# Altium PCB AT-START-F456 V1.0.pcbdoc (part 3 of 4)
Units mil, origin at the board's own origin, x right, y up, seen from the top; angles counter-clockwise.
Board outline 10942.5 x 3554 mil, 2 copper layers (Top Layer, Bottom Layer); 156 components, 201 nets, 759 pads, 796 vias.
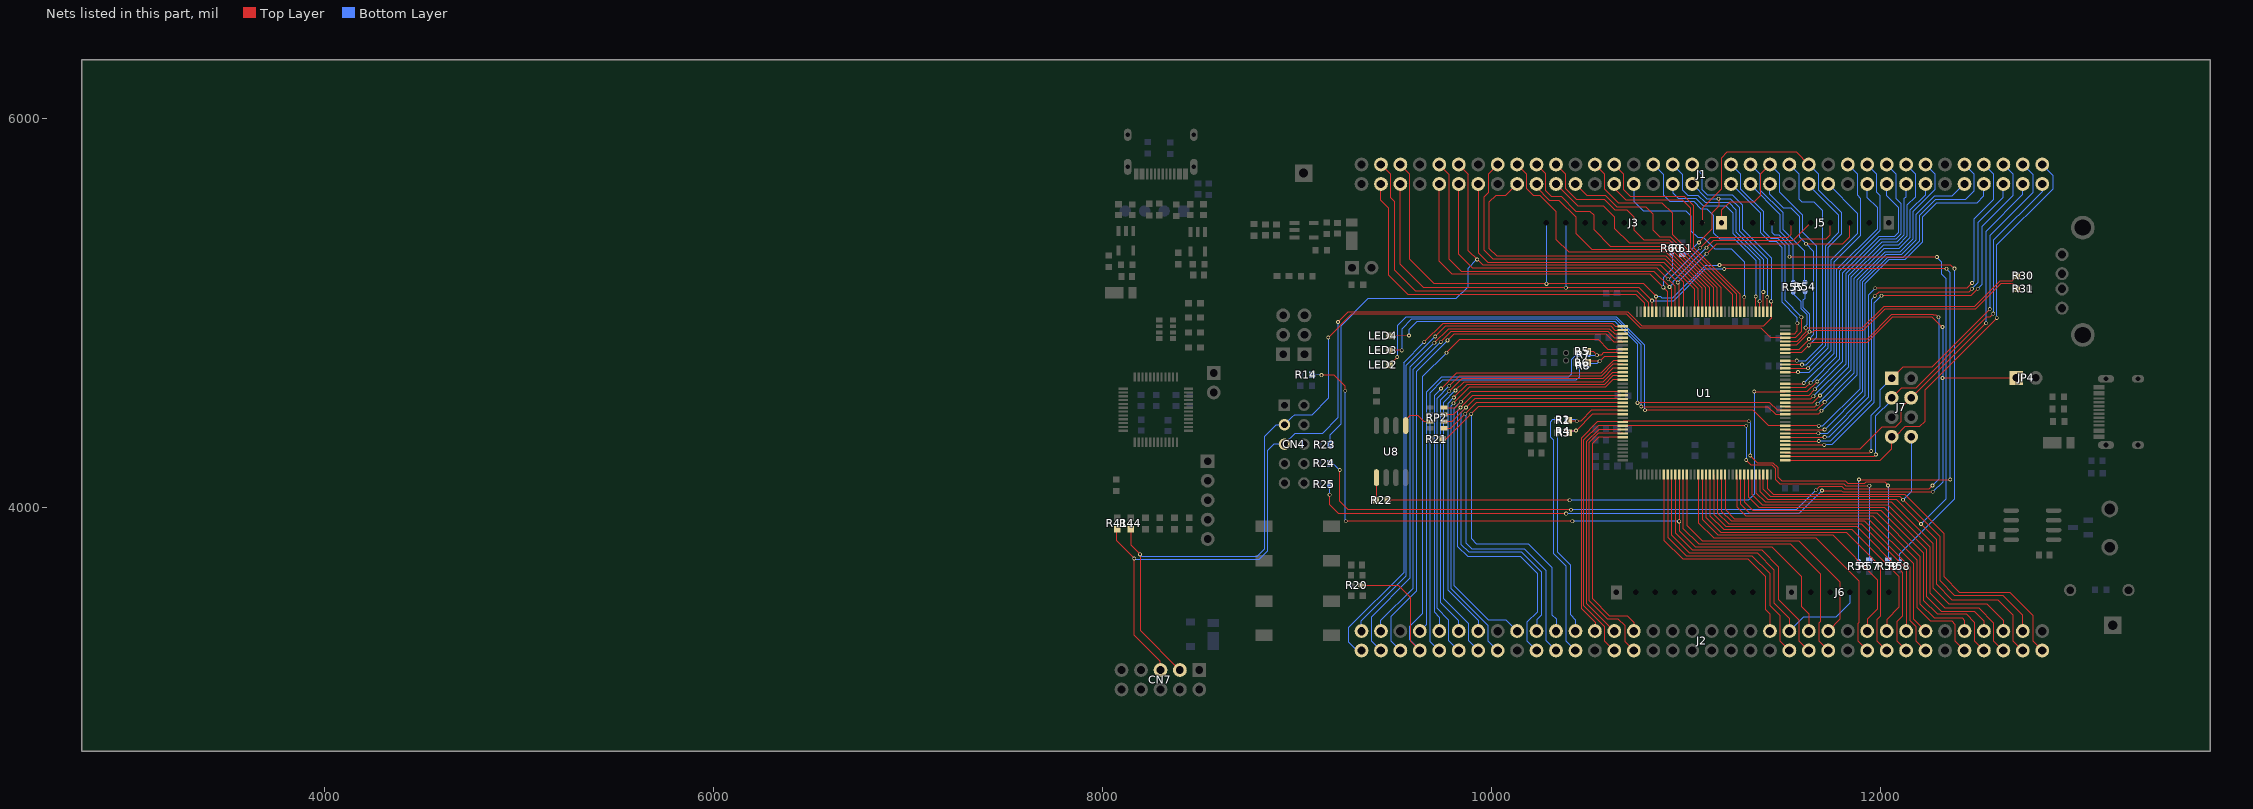
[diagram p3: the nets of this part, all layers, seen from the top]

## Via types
v1: diameter 19.7, hole 11.8, Top Layer to Bottom Layer, 419 vias
v2: diameter 19.68, hole 11.81, Top Layer to Bottom Layer, 364 vias
v3: diameter 31.5, hole 19.68, Top Layer to Bottom Layer, 12 vias
v4: diameter 27.56, hole 19.68, Top Layer to Bottom Layer, 1 vias

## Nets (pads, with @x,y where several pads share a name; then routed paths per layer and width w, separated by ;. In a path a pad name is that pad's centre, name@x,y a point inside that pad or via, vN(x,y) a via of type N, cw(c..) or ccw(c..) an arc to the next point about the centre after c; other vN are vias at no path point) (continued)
PA9: J1.29 J3.1 JP4.1 R25.2 U1.101 | length 6953.7
  Top Layer w5.98: v2(12316.57,4668.61) JP4.1@12695.57,4668.61
  Top Layer w6: v2@9165.26,4067.98 9165.26,4017.48 9211.76,3970.98 v2(10381.21,3970.97) ; J3.1@11179.86,5465.98 11179.86,5529.58 11222.26,5571.98 11346.26,5571.98 11378.26,5603.98 11378.26,5714.68 J1.29@11429.16,5765.68 ; U1.101@11508.56,4796.68 11588.96,4796.68 11628.26,4835.98 11642.08,4849.8 11926.89,4849.8 12058.57,4981.49 12264.7,4981.49 12316.11,4930.07 v2(12316.39,4930.07) ; v2(11697.01,4090.2) 11697.59,4089.61 11795.86,4089.61 11802.86,4082.61 12265.83,4082.61 v2(12266.52,4083.31)
  Bottom Layer w5.98: v2(12266.52,4083.31) 12316.57,4133.36 v2(12316.57,4668.61) 12316.57,4929.89 v2(12316.39,4930.07)
  Bottom Layer w6: R25.2@9165.16,4123.08 9165.16,4068.18 v2@9165.26,4067.98 ; v2(10381.21,3970.97) 11577.78,3970.97 v2(11697.01,4090.2) ; J1.29@11429.16,5765.68 11478.26,5716.58 11478.26,5624.38 11598.26,5504.38 11598.26,5416.88 11670.26,5344.88 11670.26,4877.98 v2@11628.26,4835.98
  other v2: 9165.21,4067.97 11628.21,4835.97
PA10: J1.30 J5.3 R24.2 U1.102 | length 6333.4
  Top Layer w6: v2(9217.21,4194.97) 9217.21,4034.97 9261.21,3990.97 v2(10406.21,3990.97) ; U1.102@11508.56,4816.38 11578.56,4816.38 v2(11630.21,4867.97) ; v2(11614.7,5358.7) 11803.86,5358.68 11839.76,5394.68 J5.3@11839.8,5465.97 ; v2@11630.26,4867.98 11928.11,4867.98 12050.98,4990.95 12051.09,4990.95 12053.61,4993.47 12269.66,4993.47 12272.18,4990.95 12284.94,4990.95 v2(12295.76,4980.13) ; v2(11664.45,4090.7) 11682.78,4109.02 11800.27,4109.02 11813.68,4095.61 12245.27,4095.61 v2(12264.74,4115.09)
  Bottom Layer w5.98: v2(12264.74,4115.09) 12296.57,4146.91 12296.57,4979.32 v2(12295.76,4980.13)
  Bottom Layer w6: R24.2@9165.76,4229.98 9182.16,4229.98 v2@9217.26,4194.98 ; v2(10406.21,3990.97) 11564.72,3990.97 v2(11664.45,4090.7) ; J1.30@11429.16,5665.68 11429.16,5612.78 11501.26,5540.78 11537.86,5540.78 11581.56,5496.98 11581.56,5391.78 v2(11614.7,5358.7) ; v2(11614.7,5358.7) 11655.27,5318.12 11655.27,5146.73 11655.27,4893.04 v2(11630.21,4867.97)
PA11: R31.1 R54.2 U1.103 | length 1571.4
  Top Layer w6: U1.103@11508.56,4835.98 11563.59,4835.98 11632.77,4905.16 v2(11632.82,4906) ; v2(11632.82,4906) 11652.43,4906 11659.92,4913.48 11909.11,4913.48 12020.91,5025.38 12486.43,5025.38 12617.1,5156.06 12674.09,5156.06 12701.32,5128.82 R31.1@12701.32,5127.69
  Bottom Layer w6: R54.2@11609.4,5114.26 11609.4,5078 11600.9,5069.51 11600.9,5028.93 11632.87,4996.96 v2@11632.87,4906.01 ; v2@11632.26,4913.98 11632.77,4913.47 v2(11632.82,4906)
PA11_E: J1.31 R54.1 | length 726
  Bottom Layer w6: J1.31@11329.16,5765.68 11380.26,5714.58 11380.26,5633.98 11497.66,5516.58 11497.66,5429.28 11608.26,5318.68 R54.1@11608.26,5155.28
PA12: R30.1 R55.2 U1.104 | length 1569.5
  Top Layer w6: U1.104@11508.56,4855.68 11566.31,4855.68 11613.36,4902.73 v2@11613.36,4926.2 ; v2(11612.72,4926.88) v2@11613.36,4926.2 ; R30.1@12701.32,5194.62 12701.32,5193.49 12675.88,5168.04 12612.14,5168.04 12482.15,5038.06 12016.64,5038.06 11904.06,4925.48 11614.08,4925.48 v2@11613.36,4926.2
  Bottom Layer w6: R55.2@11549.03,5099.37 R55.2@11549.03,5100.5 ; R55.2@11549.03,5113.47 R55.2@11549.03,5100.5 ; v2(11612.72,4926.88) 11612.67,4937.47 11620.26,4945.05 11620.26,4992.6 11588.9,5023.96 11588.9,5060.63 R55.2@11549.03,5100.5
PA12_E: J1.32 R55.1 | length 601.9
  Bottom Layer w6: J1.32@11329.16,5665.68 11329.16,5660.98 11483.06,5507.08 11483.06,5418.98 11550.16,5351.88 R55.1@11550.16,5155.28
PA13/SWDIO: CN4.3 CN7.3 J1.33 R44.2 U1.105 | length 6357.5
  Top Layer w6: R44.2@8144.46,3888.68 8144.46,3807.38 v2(8190.46,3761.38) 8190.46,3371.66 CN7.3@8395.46,3166.58 ; v2@9158.26,4875.98 9277.17,4994.9 10692.84,4994.9 10764.76,4922.98 11385.27,4922.98 11432.77,4875.38 U1.105@11508.48,4875.42 11559.66,4875.38 11590.86,4906.58 v2@11590.86,4980.18
  Bottom Layer w6: v2(8190.46,3761.38) 8199.22,3752.61 8793.57,3752.61 8832.26,3791.3 8832.26,4368.88 8891.53,4428.15 CN4.3@8933.23,4427.98 ; CN4.3@8933.26,4427.98 8970.96,4466.28 8983.16,4477.68 9072.16,4477.68 9158.26,4563.78 v2@9158.26,4875.98 ; J1.33@11229.16,5765.68 11280.26,5714.58 11280.26,5639.18 11397.56,5521.88 11397.56,5422.18 11436.26,5383.48 11470.86,5383.48 11506.76,5347.68 11506.76,5067.48 11590.86,4983.38 v2@11590.86,4980.18
  other v2: 9158.21,4875.97 11590.82,4980.14
PA14/SWCLK: CN4.5 CN7.5 J1.37 R41.2 U1.109 | length 6292.3
  Top Layer w6: R41.2@8070.46,3888.68 8070.46,3830.78 v2(8160.56,3740.58) 8161.97,3739.27 8161.97,3346.21 8295.46,3212.73 CN7.5@8295.46,3166.58 ; v2@9208.26,4955.98 9259.16,5006.88 10699.46,5006.88 10771.36,4934.98 11393.48,4934.98 11434.66,4976.15 U1.109@11434.66,5008.31 11435.16,5008.78 v2(11435.21,5061.97)
  Bottom Layer w6: v2(8160.56,3740.58) 8168.52,3732.61 8801.57,3732.61 8845.26,3776.3 8845.26,4294.08 8879.26,4328.18 ; 8880.73,4327.97 CN4.5@8933.23,4327.98 8933.23,4330.45 8984.76,4381.98 9126.96,4381.98 9208.26,4463.28 v2@9208.26,4955.98 ; J1.37@11029.16,5765.68 11078.26,5716.58 11078.26,5637.88 11106.16,5609.98 11234.26,5609.98 11286.26,5557.98 11286.26,5434.58 11435.16,5285.68 v2(11435.21,5061.97)
  other v2: 9208.21,4955.97
PA15: J1.38 R61.1 U1.110 | length 1263.8
  Top Layer w6: v2(11063.88,5365.01) 11130.86,5431.98 11130.86,5515.88 11164.96,5550.08 v2(11165,5589.98) ; U1.110@11414.97,5008.31 11415.16,5008.48 v2(11415.21,5083.97)
  Bottom Layer w6: R61.1@10979.26,5307.48 11006.36,5307.48 v2(11063.88,5365.01) ; J1.38@11029.16,5665.68 11104.86,5589.98 v2(11165,5589.98) ; v2(11165,5589.98) 11226.26,5589.98 11270.26,5545.98 11270.26,5426.18 11415.16,5281.28 v2(11415.21,5083.97)
PB0: J2.46 J6.4 U1.46 | length 1685.8
  Top Layer w6: U1.46@10922.86,4171.68 10922.86,3862.28 11014.66,3770.48 11362.76,3770.48 11449.96,3683.28 11449.96,3513.18 11529.16,3434.08 J2.46@11529.17,3367.08
  Bottom Layer w6: J2.46@11529.17,3367.08 11600.06,3437.98 11768.26,3437.98 11839.86,3509.58 J6.4@11839.86,3565.98
PB1: J2.47 U1.47 | length 1397.4
  Top Layer w6: U1.47@10942.56,4171.68 10942.56,3872.88 11029.96,3785.48 11385.76,3785.48 11472.46,3698.78 11472.46,3529.78 11578.26,3423.98 11578.26,3318.08 J2.47@11629.17,3267.08
PB2/BOOT1: J2.48 R14.2 U1.48 | length 3916.5
  Top Layer w6: v2@9123.26,4682.98 9188.46,4682.98 9245.96,4625.48 v2@9245.96,4602.58 ; v2(9248.21,3931.97) v2(10413.21,3931.97) ; U1.48@10962.26,4171.68 U1.48@10962.22,4171.68 v2(10962.21,3930.97) 10962.16,3883.98 11046.06,3800.08 11438.06,3800.08 11590.26,3647.88 11590.26,3493.88 11629.16,3454.98 J2.48@11629.17,3367.08
  Bottom Layer w6: R14.2@9072.76,4683.98 v2@9123.26,4682.98 ; v2(9245.95,4602.58) 9245.95,3934.23 v2(9248.21,3931.97) ; v2(10413.21,3931.97) 10414.21,3930.97 v2(10962.21,3930.97)
  other v2: 9123.21,4682.97
PB3: J1.61 J5.4 R23.2 U1.133 | length 4241.5
  Top Layer w6: J1.61@9829.16,5765.68 9878.26,5716.58 9878.26,5322.93 v2(9923.57,5277.61) 9923.86,5277.9 9923.86,5278.38 9952.26,5249.98 10865.2,5249.98 v2@10955.55,5159.63 ; v2@10955.56,5159.58 10962.26,5152.98 U1.133@10962.26,5008.28 ; v2(11103.68,5306.7) 11155.26,5358.28 11569.36,5358.28 11594.16,5383.18 11719.06,5383.18 11739.76,5403.78 J5.4@11739.8,5465.97
  Bottom Layer w6: R23.2@9167.76,4326.18 9167.66,4377.58 9223.86,4433.98 9223.86,4937.71 9363.38,5077.23 9817.5,5077.23 9878.26,5137.98 9878.26,5232.94 9922.93,5277.61 v2(9923.57,5277.61) ; v2@10955.55,5159.63 11102.62,5306.7 v2(11103.68,5306.7)
  other v2: 10955.55,5159.63
PB4: J1.62 J5.6 U1.134 | length 2465.4
  Top Layer w6: J1.62@9829.16,5665.68 9826.26,5662.68 9826.26,5305.98 9898.26,5233.98 10848.19,5233.98 v2(10906.68,5175.49) 10942.2,5139.97 ; 10942.16,5139.98 10942.16,5008.68 U1.134@10942.56,5008.28 ; v2(11070.58,5337.43) 11124.16,5390.98 11523.66,5390.98 11539.76,5407.08 J5.6@11539.8,5465.97
  Bottom Layer w6: v2(10906.68,5175.49) 10908.64,5175.49 v2(11070.58,5337.43)
PB5: J1.63 J5.5 U1.135 | length 2701.5
  Top Layer w6: J1.63@9729.16,5765.68 9778.26,5716.58 9778.26,5281.98 9842.26,5217.98 10831.46,5217.98 v2(10912.98,5136.49) 10922.86,5126.58 U1.135@10922.86,5008.28 ; v2(11102.89,5338.22) 11140.76,5376.08 11549.86,5376.08 J5.5@11639.8,5465.97
  Bottom Layer w6: v2(10912.98,5136.49) 10931.1,5154.61 10931.1,5166.04 11102.89,5337.82 v2(11102.89,5338.22)
PB6: J1.64 R60.2 U1.136 | length 1936.9
  Top Layer w6: J1.64@9729.16,5665.68 9729.16,5269.08 9796.26,5201.98 10813.16,5201.98 v2(10881.21,5133.97) 10903.16,5111.98 U1.136@10903.16,5008.31
  Bottom Layer w6: v2(10881.21,5133.97) 10881.16,5184.28 10926.16,5229.28 R60.2@10926.16,5312.88
PB8: J1.67 J3.10 R58.1 U1.139 | length 5484.8
  Top Layer w5.98: v2(11169.57,5248.61) 12359.89,5248.61 v2(12378.1,5230.4)
  Top Layer w6: J1.67@9529.16,5765.18 9578.26,5716.58 9578.26,5277.88 9704.26,5151.98 v2(10280.21,5151.97) 10779.26,5151.98 v2(10843.58,5087.62) 10843.56,5008.78 U1.139@10844.16,5008.18
  Bottom Layer w5.98: v2(10843.58,5087.62) 10864.56,5087.62 10871.57,5080.61 10930.57,5080.61 11098.57,5248.61 v2(11169.57,5248.61) ; R58.1@12096.95,3722.29 12096.95,3765.8 12377.97,4046.81 12377.97,5230.27 v2(12378.1,5230.4)
  Bottom Layer w6: J3.10@10279.86,5465.98 10279.86,5394.38 10280.16,5394.08 v2(10280.21,5151.97)
PB9: J1.68 J3.9 R56.1 U1.140 | length 5742.4
  Top Layer w5.98: v2(11194.57,5228.61) 12335.93,5228.61 v2(12336.82,5229.51) ; v2(11886.57,4146.25) 11886.86,4145.97 v2(12356.51,4145.97)
  Top Layer w6: J1.68@9529.16,5665.18 9529.16,5252.98 9650.26,5131.98 v2(10379.81,5131.97) 10757.16,5131.98 10823.26,5065.98 10823.26,5009.38 U1.140@10824.46,5008.18
  Bottom Layer w5.98: v2(10823.21,5065.97) 10934.92,5065.97 11097.57,5228.61 v2(11194.57,5228.61) ; R56.1@11886.22,3723.08 11886.22,4145.9 v2(11886.57,4146.25) ; v2(12336.82,5229.51) 12356.51,5209.81 v2(12356.51,4145.97)
  Bottom Layer w6: v2@10379.86,5131.98 J3.9@10379.86,5465.98
PB10: J2.69 J5.7 U1.69 | length 4423
  Top Layer w5.98: v2(11529.2,5291.33) 11530.77,5289.75 v2(12287.18,5289.75)
  Top Layer w6: U1.69@11375.66,4171.68 11375.66,4085.08 11416.86,4043.98 12078.36,4043.98 12283.36,3838.98 12283.36,3609.83 12364.6,3528.58 12600.66,3528.58 12678.26,3450.88 12678.26,3318.08 J2.69@12729.17,3267.08
  Bottom Layer w5.98: v2(12205.57,3917.61) 12206.57,3917.61 12336.61,4047.65 12336.61,5178.31 12313.07,5201.84 12313.07,5263.87 v2(12287.18,5289.75)
  Bottom Layer w6: J5.7@11439.8,5465.97 11439.76,5414.24 11452.72,5401.28 11477.16,5401.28 11529.16,5349.28 v2@11529.16,5291.38
PB11: J2.70 J7.8 U1.70 | length 2233.5
  Top Layer w6: U1.70@11395.36,4171.68 11395.36,4094.98 11433.06,4057.28 12098.9,4057.28 ; 12098.73,4057.11 12303.57,3852.27 12303.57,3624.61 12379.5,3548.68 12627.76,3548.68 12729.16,3447.28 J2.70@12729.17,3367.08
  Bottom Layer w6: v1(12113.57,4042.61) 12154.81,4083.85 J7.8@12154.81,4366.56
PB12: J1.1 J7.7 U1.73 | length 2454.6
  Top Layer w6: U1.73@11508.48,4245.5 11996.45,4245.5 12054.81,4303.85 J7.7@12054.81,4366.56 12072.51,4366.56 12122.57,4416.61 12197.57,4416.61 12224.01,4443.06 12224.01,4605.06 12595.44,4976.49 v2(12595.44,4977.43)
  Bottom Layer w6: v2(12595.44,4977.43) 12596.05,4978.03 12596.05,5352.01 12886.26,5642.35 12886.26,5708.58 J1.1@12829.16,5765.68
PB13: J1.2 J7.3 U1.74 | length 2267.8
  Top Layer w5.98: J7.3@12054.81,4566.56 12104.86,4616.61 12177.57,4616.61 12476.37,4915.41
  Top Layer w6: U1.74@11508.48,4265.19 11964.49,4265.19 v1(11973.74,4274.44) ; 12476.37,4915.41 12542.05,4981.1 12559.37,4981.1 v2(12577.22,4998.95)
  Bottom Layer w6: v1(11973.74,4274.44) 11973.74,4472.79 12054.81,4553.85 J7.3@12054.81,4566.56 ; v2(12577.22,4998.95) 12577.95,4998.95 12578.42,4999.42 12578.42,5375.47 12829.16,5626.2 J1.2@12829.16,5665.68
PB14: J1.3 J7.1 U1.75 | length 2369
  Top Layer w5.98: J7.1@12054.81,4666.56 12112.86,4724.61 12260.57,4724.61 12558.01,5022.05 v2(12559.16,5022.05)
  Top Layer w6: U1.75@11508.48,4284.87 11941.82,4284.87 v1(11949.57,4292.61)
  Bottom Layer w6: v1(11949.57,4292.61) 11949.57,4476.61 11995.57,4522.61 11995.57,4607.32 J7.1@12054.81,4666.56 ; v2(12559.16,5022.05) 12559.16,5399.2 12779.26,5619.3 12779.26,5715.58 J1.3@12729.16,5765.68
PB15: J1.4 J7.4 U1.76 | length 2134.8
  Top Layer w5.98: J7.4@12154.81,4566.56 12538.03,4949.78 v2(12540.46,4949.78)
  Top Layer w6: U1.76@11508.48,4304.56 11893.51,4304.56 12006.57,4417.61 12076.57,4417.61 12104.57,4445.61 12104.57,4516.32 J7.4@12154.81,4566.56
  Bottom Layer w6: v2(12540.46,4949.78) 12540.33,4949.91 12540.33,5423.27 12729.16,5612.25 J1.4@12729.16,5665.68
PC0: J2.26 R59.1 U1.26 | length 3293.9
  Top Layer w6: J2.26@10529.17,3367.08 10530.26,3368.08 10530.26,3411.93 10458.26,3483.93 10458.26,4359.3 10541.23,4442.28 U1.26@10671.86,4442.35 10675.56,4445.98 v2(11320.21,4445.97) ; v2(11328.21,4269.97) 11328.21,4267.98 11362.62,4233.56 11443.62,4233.56 11468.3,4208.88 11468.3,4159.58 11489.27,4138.61 11816.91,4138.61 11829.1,4126.43 11916.38,4126.43 11923.57,4133.61 12018.23,4133.61 v2(12035.97,4115.88)
  Bottom Layer w6: v2(11320.21,4445.97) 11328.21,4437.97 v2(11328.21,4269.97) ; v2(12035.97,4115.88) 12037.06,4114.79 R59.1@12037.06,3729.62
PC1: J2.27 R57.1 U1.27 | length 3299.7
  Top Layer w6: J2.27@10629.17,3267.08 10578.26,3318.08 10578.26,3391.93 10470.26,3499.93 10470.26,4347.3 10545.63,4422.68 U1.27@10671.86,4422.67 10672.26,4422.98 v2(11307.21,4422.97) ; v2(11307.21,4246.97) 11307.16,4244.03 11329.62,4221.56 11438.62,4221.56 11456.3,4203.88 11456.3,4148.34 11480.41,4124.23 11807.95,4124.23 11817.74,4114.44 v2(11940.22,4114.44)
  Bottom Layer w6: v2(11307.21,4246.97) v2(11307.21,4422.97) ; R57.1@11940.16,3727.48 11940.57,3727.89 11940.57,4114.09 v2(11940.22,4114.44)
PC2: J2.28 U1.28 | length 1245.1
  Top Layer w6: J2.28@10629.1,3367.08 10485.57,3510.61 10485.57,4340.61 10547.93,4402.98 U1.28@10671.86,4402.98
PC3: J2.29 U1.29 | length 1390.1
  Top Layer w6: U1.29@10671.86,4383.3 10545.2,4383.28 10497.57,4335.64 10497.57,3526.61 10593.57,3430.61 10647.66,3430.61 10682.26,3395.89 10682.26,3314.08 J2.29@10729.17,3267.08
PC4: J2.44 U1.44 | length 1227.3
  Top Layer w6: U1.44@10883.56,4171.68 10883.56,3834.98 10979.56,3738.98 11315.26,3738.98 11406.26,3647.98 11406.26,3478.18 11429.36,3454.98 J2.44@11429.17,3367.08
PC5: J2.45 U1.45 | length 1362.3
  Top Layer w6: U1.45@10903.16,4171.68 10903.16,3850.38 10998.06,3755.48 11336.76,3755.48 11428.26,3663.98 11428.26,3499.98 11480.26,3447.98 11480.26,3316.08 J2.45@11529.17,3267.08
PC6: J1.24 U1.96 | length 1257.2
  Top Layer w6: U1.96@11508.56,4698.28 11573.58,4698.28 v2(11573.72,4698.36)
  Bottom Layer w6: v2(11573.72,4698.36) 11632.04,4698.37 11743.96,4810.29 11743.96,5275.68 11881.46,5413.18 11881.46,5513.38 J1.24@11729.16,5665.68
PC7: J1.25 J3.2 U1.97 | length 2167
  Top Layer w6: J3.2@11079.86,5465.98 11079.86,5539.58 11178.26,5637.98 11178.26,5797.98 11208.26,5827.98 11566.86,5827.98 J1.25@11629.16,5765.68 ; U1.97@11508.56,4717.88 11624.3,4717.88 v2(11624.54,4718.06)
  Bottom Layer w6: v2(11624.54,4718.06) 11729.76,4823.34 11729.76,5341.48 11797.56,5409.18 11797.56,5516.78 11680.26,5633.98 11680.26,5714.58 J1.25@11629.16,5765.68
PC8: J1.26 U1.98 | length 1168.5
  Top Layer w6: U1.98@11508.56,4737.58 11592.77,4737.58 v2(11593.42,4736.97)
  Bottom Layer w6: v2(11593.42,4736.97) 11614.7,4736.98 11715.16,4837.44 11715.16,5348.78 11782.96,5416.58 11782.96,5505.18 11629.16,5658.98 J1.26@11629.16,5665.68
PC9: J1.27 U1.99 | length 1255
  Top Layer w6: U1.99@11508.56,4757.28 11566.78,4757.28 v2(11567.02,4757.46)
  Bottom Layer w6: J1.27@11529.16,5765.68 11580.26,5714.58 11580.26,5586.18 11594.96,5571.48 11655.66,5571.48 11699.76,5527.38 11699.76,4844.1 11613.13,4757.47 v2(11567.02,4757.46)
PC10: J1.39 U1.111 | length 1052.5
  Top Layer w6: v2(11395.21,5109.97) 11395.16,5008.38 U1.111@11395.36,5008.28
  Bottom Layer w6: J1.39@10929.16,5765.68 10978.26,5716.58 10978.26,5635.98 11006.26,5607.98 11058.26,5607.98 11095.26,5570.98 11217.26,5570.98 11254.26,5533.98 11254.26,5418.88 11395.16,5278.08 v2(11395.21,5109.97)
PC11: J1.40 U1.112 | length 963.4
  Top Layer w6: U1.112@11375.66,5008.28 11376.16,5008.88 v2(11376.21,5062.97)
  Bottom Layer w6: J1.40@10929.16,5665.68 10929.16,5620.98 10958.26,5591.98 11048.16,5591.98 11086.16,5553.98 11202.16,5553.98 11238.16,5517.98 11238.16,5412.88 11376.16,5274.98 v2(11376.21,5062.97)
PC12: J1.41 U1.113 | length 1108.7
  Top Layer w6: U1.113@11355.96,5008.28 11356.16,5008.58 v2(11356.21,5086.97)
  Bottom Layer w6: J1.41@10829.16,5765.68 10880.26,5714.58 10880.26,5609.88 10914.26,5575.98 11037.26,5575.98 11074.26,5538.98 11103.26,5538.98 11138.26,5503.98 11138.26,5415.58 11170.66,5383.18 11245.56,5383.18 11356.16,5272.48 v2(11356.21,5086.97)
PC13: J2.7 R20.2 U1.7 | length 3158.1
  Top Layer w6: R20.2@9326.5,3602.96 9518.26,3602.98 9579.26,3541.98 9579.26,3317.08 J2.7@9629.17,3267.08 ; v2(9766.21,4797.97) 9834.76,4866.58 10545.36,4866.58 10595.56,4816.38 U1.7@10671.86,4816.37
  Bottom Layer w6: J2.7@9629.16,3267.18 9629.16,3270.98 9578.26,3322.18 9578.26,3391.88 9644.21,3457.83 9644.21,4675.97 v2(9766.21,4797.97)
PC14/LEXT_IN: R5.2 R7.2 U1.8 | length 238.2
  Top Layer w5.98: R5.2@10493.59,4804.45 10519.72,4804.45 v2(10539.15,4785.02)
  Top Layer w6: v2(10539.15,4785.02) 10560.7,4785.02 10572.35,4796.68 U1.8@10671.86,4796.68
  Bottom Layer w5.98: R7.2@10493.13,4787.44 R7.2@10495.54,4785.02
  Bottom Layer w6: R7.2@10495.54,4785.02 v2(10539.15,4785.02)
PC14_E: J2.8 R7.1 | length 2151.6
  Bottom Layer w5.98: 10407.08,4687.38 10407.08,4762.4 10432.12,4787.44 R7.1@10448.73,4787.44
  Bottom Layer w6: J2.8@9629.16,3367.18 9662.26,3400.28 9662.26,4594.98 9739.75,4672.47 10392.18,4672.47 10407.08,4687.38
PC15/LEXT_OUT: R6.2 R8.2 U1.9 | length 261
  Top Layer w5.98: R6.2@10493.59,4747.72 10500.1,4754.23 v2(10553.35,4754.23)
  Top Layer w6: v2(10553.35,4754.23) 10576.09,4776.98 U1.9@10671.86,4777
  Bottom Layer w5.98: R8.2@10492.18,4731.55 10501.01,4740.37 10539.49,4740.37 v2(10553.35,4754.23)
PC15_E: J2.9 R8.1 | length 2203.5
  Bottom Layer w5.98: 10385.76,4655.38 10429.94,4655.38 10447.78,4673.22 R8.1@10447.78,4731.55
  Bottom Layer w6: J2.9@9729.17,3267.08 9680.56,3315.68 9680.56,4590.78 9745.16,4655.38 10385.76,4655.38
PD2: J1.44 U1.116 | length 1087.8
  Top Layer w6: U1.116@11296.86,5008.31 11297.16,5008.58 v2(11297.21,5083.97)
  Bottom Layer w6: J1.44@10729.16,5665.68 10729.16,5576.98 10778.26,5527.98 10996.26,5527.98 11022.26,5501.98 11022.26,5424.98 11056.76,5390.48 11086.76,5390.48 11144.26,5332.98 11229.06,5332.98 11297.16,5264.88 v2(11297.21,5083.97)
PD3: J1.45 U1.117 | length 1188.7
  Top Layer w6: J1.45@10629.18,5765.65 10678.21,5716.62 10678.21,5641.97 ; 10678.26,5641.98 10678.26,5635.88 10714.16,5599.98 10992.16,5599.98 11038.26,5553.98 11038.26,5336.98 11277.26,5097.88 U1.117@11277.26,5008.28
PD4: J1.46 U1.118 | length 1087.6
  Top Layer w6: J1.46@10629.16,5665.68 10629.16,5642.98 10690.16,5581.98 10980.26,5581.98 11022.26,5539.98 11022.26,5333.98 11257.56,5098.58 U1.118@11257.56,5008.28
PD5: J1.47 U1.119 | length 1182.1
  Top Layer w6: J1.47@10529.16,5765.68 10580.26,5714.58 10580.26,5637.98 10652.26,5565.98 10876.26,5565.98 10928.26,5513.98 10928.26,5404.98 11237.86,5095.28 U1.119@11237.86,5008.28
PD6: J1.50 U1.122 | length 1167.3
  Top Layer w6: J1.50@10429.16,5665.68 10488.86,5605.98 10584.26,5605.98 10644.26,5545.98 10792.26,5545.98 10828.26,5509.88 10828.26,5427.98 10864.26,5391.98 10920.26,5391.98 11178.76,5133.38 U1.122@11178.76,5008.28 ; J1.50@10429.18,5665.65 J1.50@10446.21,5648.62
PD7: J1.51 U1.123 | length 1298.3
  Top Layer w6: J1.51@10329.16,5765.68 10380.26,5714.58 10380.26,5640.58 10436.86,5583.98 10580.26,5583.98 10634.26,5529.98 10694.26,5529.98 10730.26,5493.98 10730.26,5427.88 10782.26,5375.98 10915.26,5375.98 11159.16,5131.98 U1.123@11159.16,5008.28
PD8: J1.5 U1.77 | length 2356.5
  Top Layer w6: U1.77@11508.56,4324.18 v2@11708.26,4324.18 ; v2(12002.35,5091.28) 12461.1,5091.28 v2(12497.09,5127.27)
  Bottom Layer w6: v2@11708.26,4324.18 11747.46,4324.18 11962.99,4539.71 11962.99,5051.92 v2(12002.35,5091.28) ; v2(12497.09,5127.27) 12520.94,5151.12 12520.94,5448.98 12680.07,5608.11 12680.07,5714.76 J1.5@12629.18,5765.65
  other v2: 11708.21,4324.22
PD9: J1.6 U1.78 | length 2192.3
  Top Layer w6: U1.78@11508.56,4343.88 v2@11680.26,4343.88 ; v2(11968.3,5090.41) 11987.99,5110.1 12450.11,5110.1 v2(12467.26,5127.26)
  Bottom Layer w6: v2@11680.26,4343.88 11740.16,4343.88 11948.8,4552.53 11948.8,5070.92 v2(11968.3,5090.41) ; v2(12467.26,5127.26) 12500.5,5160.5 12500.5,5468.55 12629.18,5597.22 J1.6@12629.18,5665.65
  other v2: 11680.21,4343.91
PD10: J1.7 U1.79 | length 2272.4
  Top Layer w6: U1.79@11508.56,4363.58 11508.86,4363.98 v2@11710.26,4363.98 ; v2(11970.84,5129.82) 12441.78,5129.82 v2(12468.73,5156.78)
  Bottom Layer w6: v2@11710.26,4363.98 11731.26,4363.98 11935.41,4568.13 11935.41,5094.4 v2(11970.84,5129.82) ; v2(12468.73,5156.78) 12480.14,5168.18 12480.14,5487.19 12579.2,5586.25 12579.2,5715.62 J1.7@12529.18,5765.65
  other v2: 11710.21,4363.97
PD11: J1.8 U1.80 | length 2001.5
  Top Layer w6: U1.80@11508.56,4383.28 11509.26,4383.98 v2@11678.26,4383.98
  Bottom Layer w6: v2@11678.26,4383.98 11725.26,4383.98 11920.26,4578.98 11920.26,5155.98 12042.26,5277.98 12124.26,5277.98 12214.26,5367.98 12214.26,5497.98 12286.26,5569.98 12494.16,5569.98 12529.16,5604.98 J1.8@12529.16,5665.68
  other v2: 11678.21,4383.97
PD12: J1.9 U1.81 | length 2039.9
  Top Layer w6: U1.81@11508.56,4402.98 v2@11710.26,4402.98
  Bottom Layer w6: v2@11710.26,4402.98 11906.26,4598.98 11906.26,5161.98 12034.26,5289.98 12114.26,5289.98 12198.26,5373.98 12198.26,5503.98 12282.26,5587.98 12436.26,5587.98 12478.26,5629.98 12478.26,5716.58 J1.9@12429.16,5765.68
  other v2: 11710.21,4402.95
PD13: J1.10 LED2.2 U1.82 | length 4498.8
  Top Layer w6: LED2.2@9472.01,4735.2 9512.66,4775.88 v2(9512.71,4776.37) ; v2(10786.63,4502.66) 11343.47,4502.66 11423.45,4422.68 11508.56,4422.68 11509.16,4421.98 v2(11680.21,4421.97)
  Bottom Layer w6: v2(9512.71,4776.37) 9512.66,4937.58 9556.73,4981.58 10642.76,4981.58 10786.63,4837.71 v2(10786.63,4502.66) ; v2(11680.21,4421.97) 11701.26,4421.98 11892.26,4612.98 11892.26,5167.98 12028.26,5303.98 12106.86,5303.98 12182.26,5379.38 12182.26,5509.98 12276.26,5603.98 12367.46,5603.98 J1.10@12429.16,5665.68
PD14: J1.13 LED3.2 U1.85 | length 4325.1
  Top Layer w6: LED3.2@9472.06,4810.18 9472.16,4810.28 v2(9535.73,4810.28) ; v2(10767.03,4521.5) 11418.64,4521.5 11458.46,4481.68 11508.56,4481.68 11508.56,4484.78 11679.06,4484.78 v2@11694.26,4499.98
  Bottom Layer w6: v2(9535.73,4810.28) 9535.73,4919.16 9586.16,4969.58 10637.79,4969.58 10767.26,4840.11 10767.26,4521.73 v2(10767.03,4521.5) ; v2@11694.26,4499.98 11878.26,4683.98 11878.26,5173.98 12022.26,5317.98 12099.16,5317.98 12166.26,5385.08 12166.26,5524.48 12280.26,5638.58 12280.26,5714.58 J1.13@12229.16,5765.68
  other v2: 11694.21,4499.97
PD15: J1.14 LED4.2 U1.86 | length 4075.4
  Top Layer w6: LED4.2@9472.06,4886.48 v2(9573.38,4887.09) ; v2(10748.42,4540.34) 11429.39,4540.34 11468.36,4501.38 11508.56,4501.38 11667.66,4501.38 v2(11710.21,4543.97) ; J1.14@12229.16,5640.68 J1.14@12229.16,5665.68
  Bottom Layer w6: v2(9573.38,4887.09) 9573.36,4916.98 9613.96,4957.58 10632.82,4957.58 10748.84,4841.56 10748.84,4540.77 v2(10748.42,4540.34) ; v2(11710.21,4543.97) 11862.26,4695.98 11862.26,5179.98 12016.26,5333.98 12093.46,5333.98 12150.76,5391.28 12150.76,5532.28 12229.16,5610.68 J1.14@12229.16,5665.68
PE0: J1.69 U1.141 | length 1994.3
  Top Layer w6: J1.69@9429.16,5765.18 9480.26,5714.58 9480.26,5593.88 9498.96,5575.18 9498.96,5221.28 9607.11,5113.13 10746.41,5113.13 10804.76,5054.78 U1.141@10804.76,5008.18
PE1: J1.70 U1.142 | length 1905
  Top Layer w6: J1.70@9429.16,5665.18 9429.16,5582.98 9470.26,5541.88 9470.26,5195.88 9570.67,5095.57 10742.37,5095.57 10785.06,5052.88 U1.142@10785.06,5008.18
PE2: J2.1 U1.1 | length 2854.9
  Top Layer w6: v2(9652.16,4853.98) 9748.26,4950.08 10618.26,4950.08 10633.96,4934.48 U1.1@10671.86,4934.48
  Bottom Layer w6: J2.1@9329.17,3267.08 9307.16,3267.08 9262.26,3311.98 9262.26,3383.98 9545.96,3667.68 9545.96,4747.78 v2(9652.16,4853.98)
PE3: J2.2 U1.2 | length 2667
  Top Layer w6: v2(9708.16,4881.98) 9762.56,4936.38 10610.76,4936.38 10632.36,4914.78 U1.2@10671.86,4914.79
  Bottom Layer w6: J2.2@9329.16,3367.18 9329.16,3419.48 9560.26,3650.58 9560.26,4734.08 v2(9708.16,4881.98)
PE4: J2.3 U1.3 | length 2747.9
  Top Layer w6: v2(9703.83,4849.3) 9777.11,4922.58 10603.26,4922.58 10630.76,4895.08 U1.3@10671.86,4895.11
  Bottom Layer w6: J2.3@9429.17,3267.08 9378.26,3318.08 9378.26,3437.48 9578.26,3637.48 9578.26,4723.73 v2(9703.83,4849.3)
PE5: J2.4 U1.4 | length 2586.6
  Top Layer w6: v2(9736.21,4853.97) 9791.36,4909.18 10595.36,4909.18 10629.16,4875.38 U1.4@10671.86,4875.42
  Bottom Layer w6: J2.4@9429.17,3367.08 9429.16,3421.38 9594.26,3586.48 9594.26,4711.98 v2(9736.21,4853.97)
PE6: J2.5 U1.5 | length 2664.6
  Top Layer w6: v2(9771.79,4861.65) 9805.52,4895.38 10585.96,4895.38 10625.66,4855.68 U1.5@10671.86,4855.74
  Bottom Layer w6: J2.5@9529.16,3267.18 9481.96,3314.38 9481.96,3444.28 9612.26,3574.58 9612.26,4702.12 v2(9771.79,4861.65)
PE7: J2.58 U1.58 | length 1605.7
  Top Layer w6: U1.58@11159.16,4171.68 11159.16,3975.88 11216.06,3918.98 11897.66,3918.98 12129.16,3687.48 J2.58@12129.17,3367.08
PE8: J2.59 U1.59 | length 1740.3
  Top Layer w6: U1.59@11178.76,4171.68 11178.76,3984.18 11229.96,3932.98 11913.96,3932.98 12147.96,3698.98 12147.96,3422.08 12178.26,3391.68 12178.26,3318.08 J2.59@12229.17,3267.08
PE9: J2.60 U1.60 | length 1635.5
  Top Layer w6: U1.60@11198.46,4171.68 11198.46,3992.68 11245.36,3945.78 11935.06,3945.78 12164.76,3716.08 12164.76,3431.48 J2.60@12229.17,3367.08
PE10: J2.63 U1.63 | length 1835.9
  Top Layer w6: U1.63@11257.56,4171.68 11257.56,4006.68 11304.26,3959.98 11956.66,3959.98 12183.66,3733.08 12183.66,3490.58 12254.26,3419.98 12363.16,3419.98 12380.26,3402.88 12380.26,3316.08 J2.63@12429.17,3267.08
PE11: J2.64 U1.64 | length 1749.5
  Top Layer w6: U1.64@11277.26,4171.68 11277.26,4020.88 11323.96,3974.18 11978.36,3974.18 12200.56,3751.98 12200.56,3508.18 12272.76,3435.98 12416.86,3435.98 12429.16,3423.68 J2.64@12429.17,3367.08
PE12: J2.65 U1.65 | length 1887.8
  Top Layer w6: U1.65@11296.86,4171.68 11296.86,4031.28 11339.76,3988.38 11998.46,3988.38 12217.86,3768.98 12217.86,3525.98 12288.86,3454.98 12437.26,3454.98 12480.26,3411.98 12480.26,3316.08 J2.65@12529.17,3267.08
PE13: J2.66 U1.66 | length 1784.8
  Top Layer w6: U1.66@11316.56,4171.68 11316.56,4056.58 11370.56,4002.58 12017.36,4002.58 12233.26,3786.68 12233.26,3546.78 12310.06,3469.98 12479.06,3469.98 12529.16,3419.88 J2.66@12529.17,3367.08
PE14: J2.67 U1.67 | length 1920.6
  Top Layer w6: U1.67@11336.26,4171.68 11336.26,4069.88 11389.36,4016.78 12035.46,4016.78 12250.66,3801.58 12250.66,3562.78 12327.46,3485.98 12501.66,3485.98 12578.26,3409.38 12578.26,3318.08 J2.67@12629.17,3267.08
PE15: J2.68 U1.68 | length 1827.5
  Top Layer w6: U1.68@11355.96,4171.68 11355.96,4079.18 11404.26,4030.98 12053.96,4030.98 12266.36,3818.58 12266.36,3588.48 12347.96,3506.88 12544.16,3506.88 12629.16,3421.88 J2.68@12629.17,3367.08
PF0: J2.10 U1.10 | length 2266
  Top Layer w6: v2@9738.26,4613.98 9817.16,4692.88 10559.16,4692.88 10623.56,4757.28 U1.10@10671.86,4757.31
  Bottom Layer w6: J2.10@9729.26,3367.08 9729.26,3438.98 9702.26,3465.88 9702.26,4577.98 v2@9738.26,4613.98
  other v2: 9738.21,4613.97
PF1: J2.11 U1.11 | length 2370.2
  Top Layer w6: v2(9780.26,4627.98) 9830.56,4678.28 10562.56,4678.28 10621.86,4737.58 U1.11@10671.86,4737.63
  Bottom Layer w6: v2(9780.26,4627.98) 9717.36,4565.08 9717.36,3484.78 9778.26,3423.88 9778.26,3318.08 J2.11@9829.16,3267.18
PF2: J2.12 U1.12 | length 2230
  Top Layer w6: v2(9780.26,4599.98) 9844.36,4664.08 10568.36,4664.08 10622.16,4717.88 U1.12@10671.86,4717.94
  Bottom Layer w6: v2(9780.26,4599.98) 9736.26,4555.98 9736.26,3513.48 9829.16,3420.48 J2.12@9829.17,3367.08
PF3: J2.13 U1.13 | length 2334.4
  Top Layer w6: v2(9812.26,4603.98) 9856.96,4648.68 10571.76,4648.68 10621.36,4698.28 U1.13@10671.86,4698.26
  Bottom Layer w6: v2(9812.26,4603.98) 9751.26,4542.98 9751.26,3533.58 9880.26,3404.48 9880.26,3316.18 J2.13@9929.16,3267.18
PF4: J2.14 U1.14 | length 2192.5
  Top Layer w6: v2@9804.26,4567.98 9870.46,4634.18 10576.36,4634.18 10620.76,4678.58 U1.14@10671.86,4678.57
  Bottom Layer w6: v2@9804.26,4567.98 9772.26,4535.98 9772.26,3578.68 9929.16,3421.78 J2.14@9929.16,3367.18
  other v2: 9804.21,4567.97
PF5: J2.15 U1.15 | length 2295.9
  Top Layer w6: v2(9802.21,4537.97) 9884.16,4619.98 10582.26,4619.98 10621.16,4658.88 U1.15@10671.86,4658.89
  Bottom Layer w6: v2(9802.21,4537.97) 9788.26,4523.18 9788.26,3587.98 9978.26,3397.88 9978.26,3318.08 J2.15@10029.17,3267.08
PF6: J2.18 RP2.4 U1.18 | length 2334.4
  Top Layer w6: RP2.4@9753.18,4516.15 9810.38,4516.15 v2(9840.21,4545.97) 9894.02,4599.78 U1.18@10671.86,4599.83
  Bottom Layer w6: v2(9840.21,4545.97) 9804.26,4509.98 9804.26,3601.88 9980.26,3425.88 10070.36,3425.88 J2.18@10129.16,3367.18
PF7: J2.19 RP2.3 U1.19 | length 2587.3
  Top Layer w6: RP2.3@9753.77,4480.48 cw(c9753.77,4481.3) RP2.3@9753.18,4480.72 9802.95,4480.72 v2(9838.21,4515.97) cw(c9838.28,4515.97) v2(9838.21,4515.97) 9861,4538.79 9902.37,4580.16 U1.19@10671.86,4580.18 ; 9960.77,4580.16 cw(c9960.77,4580.09) 9960.82,4580.14
  Bottom Layer w6: v2@9838.26,4515.98 9822.26,4499.98 9822.26,3803.88 9874.56,3751.58 10145.06,3751.58 10231.76,3664.88 10231.76,3464.78 10178.26,3411.28 10178.26,3318.08 J2.19@10229.16,3267.18
PF8: J2.20 RP2.2 U1.20 | length 2467.4
  Top Layer w6: RP2.2@9754.46,4445.81 ccw(c9754.46,4444.01) RP2.2@9753.18,4445.28 9795.51,4445.28 v2(9866.21,4515.97) 9910.7,4560.46 U1.20@10671.86,4560.46
  Bottom Layer w6: v2(9866.21,4515.97) 9840.26,4489.98 9840.26,3813.88 9880.26,3773.98 10150.66,3773.98 10253.86,3670.78 10253.86,3449.38 10229.16,3424.68 J2.20@10229.17,3367.08
PF9: J2.21 RP2.1 U1.21 | length 2542.3
  Top Layer w6: RP2.1@9753.89,4409.56 cw(c9753.89,4410.55) RP2.1@9753.18,4409.85 9788.08,4409.85 v2(9862.21,4483.97) 9919.02,4540.78 U1.21@10671.86,4540.78
  Bottom Layer w6: v2(9862.21,4483.97) 9864.26,4481.88 9864.26,3820.78 9896.06,3788.98 10166.36,3788.98 10276.26,3679.08 10276.26,3320.08 J2.21@10329.17,3267.08
PF10: J2.22 R21.1 U1.22 | length 2450
  Top Layer w6: R21.1@9744.84,4353.85 9763.43,4353.85 v2(9893.22,4483.63) 9930.67,4521.08 U1.22@10671.86,4521.09 ; v2@9899.22,4483.63 cw(c9900.17,4483.63) v2@9899.5,4484.31
  Bottom Layer w6: v2(9893.22,4483.63) 9893.22,3843.86 9920.1,3816.98 10186.05,3816.98 10307.4,3695.63 10307.4,3451.35 10329.18,3429.57 J2.22@10329.17,3367.08
PF11: J2.49 U1.49 | length 1497.2
  Top Layer w6: U1.49@10981.96,4171.68 10981.96,3896.18 11062.36,3815.78 11534.46,3815.78 11688.26,3661.98 11688.26,3413.98 11680.26,3405.98 11680.26,3316.08 J2.49@11729.17,3267.08
PF12: J2.50 U1.50 | length 1445.9
  Top Layer w6: U1.50@11001.66,4171.68 11001.66,3910.68 11081.96,3830.38 11577.96,3830.38 11788.86,3619.48 11788.86,3426.78 J2.50@11729.17,3367.08
PF13: J2.53 U1.53 | length 1575.8
  Top Layer w6: U1.53@11060.66,4171.68 11060.66,3924.48 11138.96,3846.18 11664.56,3846.18 11884.56,3626.18 11884.56,3409.98 11880.26,3405.68 11880.26,3316.08 J2.53@11929.17,3267.08
PF14: J2.54 U1.54 | length 1544.8
  Top Layer w6: U1.54@11080.36,4171.68 11080.36,3940.78 11160.06,3861.08 11751.16,3861.08 11980.26,3631.98 11980.26,3478.88 11929.16,3427.78 J2.54@11929.17,3367.08
PF15: J2.55 U1.55 | length 1683.1
  Top Layer w6: U1.55@11100.06,4171.68 11100.06,3951.08 11175.46,3875.68 11822.06,3875.68 11996.26,3701.48 11996.26,3442.88 11978.26,3424.88 11978.26,3318.08 J2.55@12029.17,3267.08
PG0: J2.56 U1.56 | length 1620.4
  Top Layer w6: U1.56@11119.76,4171.68 11119.76,3960.88 11190.36,3890.28 11850.66,3890.28 12092.26,3648.68 12092.26,3488.38 12029.16,3425.28 J2.56@12029.17,3367.08
PG1: J2.57 U1.57 | length 1733
  Top Layer w6: U1.57@11139.46,4171.68 11139.46,3967.48 11202.06,3904.98 11874.96,3904.98 12109.56,3670.38 12109.56,3443.88 12080.26,3414.58 12080.26,3316.08 J2.57@12129.17,3267.08
PG2: J1.15 U1.87 | length 1675.9
  Top Layer w6: U1.87@11508.56,4521.08 11659.26,4521.08 v2@11674.26,4535.98
  Bottom Layer w6: v2@11674.26,4535.98 11848.26,4709.98 11848.26,5187.98 12014.26,5353.98 12091.46,5353.98 12136.26,5398.78 12136.26,5557.98 12178.26,5599.98 12178.26,5716.58 J1.15@12129.16,5765.68
  other v2: 11674.21,4535.97
PG3: J1.16 U1.88 | length 1509.4
  Top Layer w6: U1.88@11508.56,4540.78 11648.96,4540.78 v2(11686.21,4577.97)
  Bottom Layer w6: v2(11686.21,4577.97) 11834.26,4725.98 11834.26,5195.98 12006.26,5367.98 12083.36,5367.98 12120.26,5404.88 12120.26,5592.08 12129.16,5600.98 J1.16@12129.16,5665.68
PG4: J1.17 U1.89 | length 1605.8
  Top Layer w6: U1.89@11508.56,4560.48 11638.66,4560.48 v2(11652.21,4573.97)
  Bottom Layer w6: v2(11652.21,4573.97) 11820.26,4741.98 11820.26,5205.98 11998.26,5383.98 12077.66,5383.98 12104.26,5410.58 12104.26,5563.98 12078.26,5589.98 12078.26,5716.58 J1.17@12029.16,5765.68
PG5: J1.18 U1.90 | length 1469.5
  Top Layer w6: U1.90@11508.56,4580.08 11630.36,4580.08 v2(11660.21,4609.97)
  Bottom Layer w6: v2(11660.21,4609.97) 11804.26,4753.98 11804.26,5209.98 11992.26,5397.98 12071.16,5397.98 12090.26,5416.98 12090.26,5543.98 12029.16,5604.98 J1.18@12029.16,5665.68
PG6: J1.19 R22.1 U1.91 | length 4051.1
  Top Layer w6: R22.1@9460.96,4039.98 v2@10399.26,4039.98 ; v2(11348.74,4598.68) 11507.47,4598.69 11508.56,4599.78 11622.06,4599.78 v2(11672.21,4649.97)
  Bottom Layer w6: v2@10399.26,4039.98 11318.26,4039.98 11348.69,4070.41 v2(11348.74,4598.68) ; v2(11672.21,4649.97) 11788.26,4765.98 11788.26,5219.98 11996.26,5427.98 11996.26,5605.98 11978.26,5623.98 11978.26,5716.58 J1.19@11929.16,5765.68
  other v2: 10399.21,4039.97
PG7: J1.20 U1.92 | length 1326
  Top Layer w6: U1.92@11508.56,4619.48 11613.76,4619.48 v2@11638.26,4643.98
  Bottom Layer w6: v2@11638.26,4643.98 11773.46,4779.18 11773.46,5227.18 11982.26,5435.98 11982.26,5542.78 11929.16,5595.88 J1.20@11929.16,5665.68
  other v2: 11638.21,4643.97
PG8: J1.21 U1.93 | length 1370
  Top Layer w6: U1.93@11508.56,4639.18 11599.19,4639.18 v2@11602.82,4642.82
  Bottom Layer w6: v2@11602.82,4642.82 11605.09,4642.82 11758.86,4796.58 11758.86,5264.58 11897.16,5402.88 11897.16,5590.78 11880.26,5607.68 11880.26,5714.58 J1.21@11829.16,5765.68
  other v2: 11602.87,4642.81
PG9: J1.52 U1.124 | length 1212.9
  Top Layer w6: J1.52@10329.16,5665.68 10442.86,5551.98 10574.16,5551.98 10632.26,5493.88 10632.26,5435.98 10708.26,5359.98 10911.16,5359.98 11139.46,5131.68 U1.124@11139.46,5008.28 ; J1.52@10329.18,5665.65 J1.52@10346.21,5648.62
PG10: J1.53 U1.125 | length 1371.6
  Top Layer w6: J1.53@10229.16,5765.68 10276.26,5718.58 10276.26,5631.98 10308.26,5599.98 10358.26,5599.98 10434.26,5523.98 10506.16,5523.98 10526.26,5503.98 10526.26,5429.18 10611.36,5343.98 10908.16,5343.98 11119.76,5132.38 U1.125@11119.76,5008.28
PG11: J1.54 U1.126 | length 1274.2
  Top Layer w6: J1.54@10229.16,5665.68 10229.16,5648.98 10298.16,5579.98 10346.26,5579.98 10432.26,5493.98 10432.26,5409.98 10514.26,5327.98 10903.29,5327.98 11099.21,5132.06 11099.26,5009.18 U1.126@11100.06,5008.28
PG12: J1.55 U1.127 | length 1463.6
  Top Layer w6: J1.55@10129.16,5765.68 10178.26,5716.58 10178.26,5641.98 10214.26,5605.98 10248.26,5605.98 10330.26,5523.98 10330.26,5379.98 10396.26,5313.98 10895.26,5313.98 11080.36,5128.78 U1.127@11080.36,5008.28
PG13: J1.56 U1.128 | length 1702.1
  Top Layer w6: J1.56@10129.16,5665.68 10069.46,5605.98 10018.26,5605.98 9984.57,5572.29 9984.57,5335.62 10024.22,5295.97 10893.3,5295.97 11059.21,5130.06 11059.26,5009.78 U1.128@11060.66,5008.28
PG14: J1.57 U1.129 | length 1753.7
  Top Layer w6: J1.57@10029.16,5765.68 9980.26,5716.68 9980.26,5619.98 9957.57,5597.29 9957.57,5326.37 10003.96,5279.98 10888.06,5279.98 11039.86,5128.18 11039.86,5009.38 U1.129@11040.96,5008.31
PG15: J1.60 U1.132 | length 1624.2
  Top Layer w6: J1.60@9929.16,5665.68 9929.16,5312.98 9978.23,5263.98 10882.26,5263.98 10983.21,5163.03 10983.26,5009.48 U1.132@10981.96,5008.28
PH0/HEXT_IN: R1.2 R2.2 U1.23 | length 357.4
  Top Layer w6: R1.2@10387.76,4447.98 10389.56,4446.18 v2(10435.86,4446.18) 10455.13,4446.18 10510.33,4501.38 U1.23@10671.86,4501.41
  Bottom Layer w6: R2.2@10388.85,4452.62 10429.42,4452.62 v2(10435.86,4446.18)
PH0_E: J2.23 R2.1 | length 1278.9
  Bottom Layer w6: R2.1@10344.45,4452.62 10309.57,4452.62 10298.76,4441.8 10298.76,4365.43 10314.46,4349.73 10314.46,3767.38 10379.46,3702.28 10379.46,3316.78 J2.23@10429.17,3267.08
PH1/HEXT_OUT: R3.2 R4.2 U1.24 | length 365.2
  Top Layer w6: R3.2@10387.76,4393.98 10428.26,4393.98 v2(10432.26,4397.98) 10515.96,4481.68 U1.24@10671.86,4481.72
  Bottom Layer w6: R4.2@10388.85,4394.62 10428.9,4394.62 v2(10432.26,4397.98)
PH1_E: J2.24 R4.1 | length 1063.9
  Bottom Layer w6: R4.1@10335.06,4391.98 10335.06,3775.08 10401.16,3708.98 10401.16,3453.88 10429.16,3425.88 J2.24@10429.17,3367.08
PH2: J1.34 U1.106 | length 986.1
  Top Layer w6: U1.106@11508.56,4895.08 11555.36,4895.08 11570.16,4909.88 v2@11570.16,4949.38
  Bottom Layer w6: J1.34@11229.16,5665.68 11230.56,5665.68 11381.86,5514.38 11381.86,5413.88 11428.36,5367.38 11463.36,5367.38 11491.76,5338.98 11491.76,5056.43 11570.16,4978.03 v2@11570.16,4949.38
  other v2: 11570.17,4949.34
PH3: J2.71 U1.71 | length 2036.8
  Top Layer w6: U1.71@11415.06,4171.68 11415.06,4101.68 11446.53,4070.32 12121.41,4070.32 12322.57,3869.17 12322.57,3648.61 12403.6,3567.58 12661.55,3567.58 12780.26,3448.87 12780.26,3316.08 J2.71@12829.17,3267.08
PH4: J2.30 U1.30 | length 1275.9
  Top Layer w6: U1.30@10671.86,4363.61 10548.56,4363.61 10515.57,4330.61 10515.57,3534.61 10603.57,3446.61 10695.57,3446.61 10729.17,3413.01 J2.30@10729.17,3367.08
QSPI1_CS: R22.2 U8.1 | length 116
  Top Layer w6: R22.2@9405.96,4039.98 9406.16,4040.18 U8.1@9406.16,4155.92
QSPI1_IO0: RP2.7 U8.5 | length 176.4
  Top Layer w6: U8.5@9556.16,4423.64 9556.16,4453.17 9579.6,4476.61 9617.57,4476.61 9648.91,4445.28 RP2.7@9680.35,4445.28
